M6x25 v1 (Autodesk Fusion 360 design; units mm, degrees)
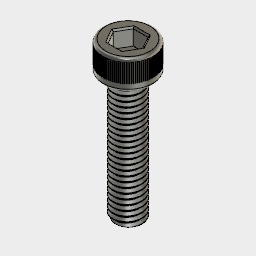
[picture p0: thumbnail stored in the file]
sketch "スケッチ1"
  circle C1 centre (0, 0) radius 3
  circle C2 centre (0, 0) radius 5
  dimension "d1" diameter C1 = 6
  dimension "d2" diameter C2 = 10
extrude "押し出し1" new body sketch "スケッチ1" blind 5.8
sketch "スケッチ2" plane through (0, 0, 5.8) normal (0, 0, 1) x axis (-1, 0, 0)
  line L1 (-1.4722, -2.55) -> (-2.9445, 0)
  line L2 (1.4722, -2.55) -> (-1.4722, -2.55)
  line L3 (2.9445, 0) -> (1.4722, -2.55)
  line L4 (1.4722, 2.55) -> (2.9445, 0)
  line L5 (-1.4722, 2.55) -> (1.4722, 2.55)
  line L6 (-2.9445, 0) -> (-1.4722, 2.55)
  circle C1 centre (0, 0) radius 5
  dimension "d5" distance L2 L5 = 5.1
work_plane "作業平面" sketch "スケッチ2" AlongDistance -0.75
extrude "押し出し2" cut sketch "スケッチ2" profile of L1 L2 L3 L4 L5 L6 against normal blind 3.3
chamfer "面取り" distance 0.3
sketch "スケッチ3" plane through (0, 0, 5.05) normal (0, 0, 1) x axis (1, 0, 0)
  line L1 (-0.05, 4.9497) -> (-0.05, 4.9997)
  line L2 (0.05, 4.9497) -> (-0.05, 4.9497)
  line L3 (0.05, 4.9997) -> (0.05, 4.9497)
  circle C1 centre (0, 0) radius 5
  point P4 (-0.05, 4.9497)
  point P5 (0.05, 4.9497)
  point P3 (-0.05, 4.9997)
  point P6 (0.05, 4.9997)
  dimension "d18" distance P4 P5 = 0.1
  dimension "d19" distance P3 P4 = 0.05
  dimension "d20" distance P5 P6 = 0.05 (= "d19")
extrude "押し出し3" cut sketch "スケッチ3" against normal blind 3.6
work_axis "作業軸"
circular_pattern "C パターン" countU 100 TotalAngle 360
fillet "フィレット1" radius 0.6
extrude "押し出し4" add sketch "スケッチ1" profile of C1 blind -25
thread "ねじ"
fillet "フィレット2" sketch "スケッチ3" radius 0.5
